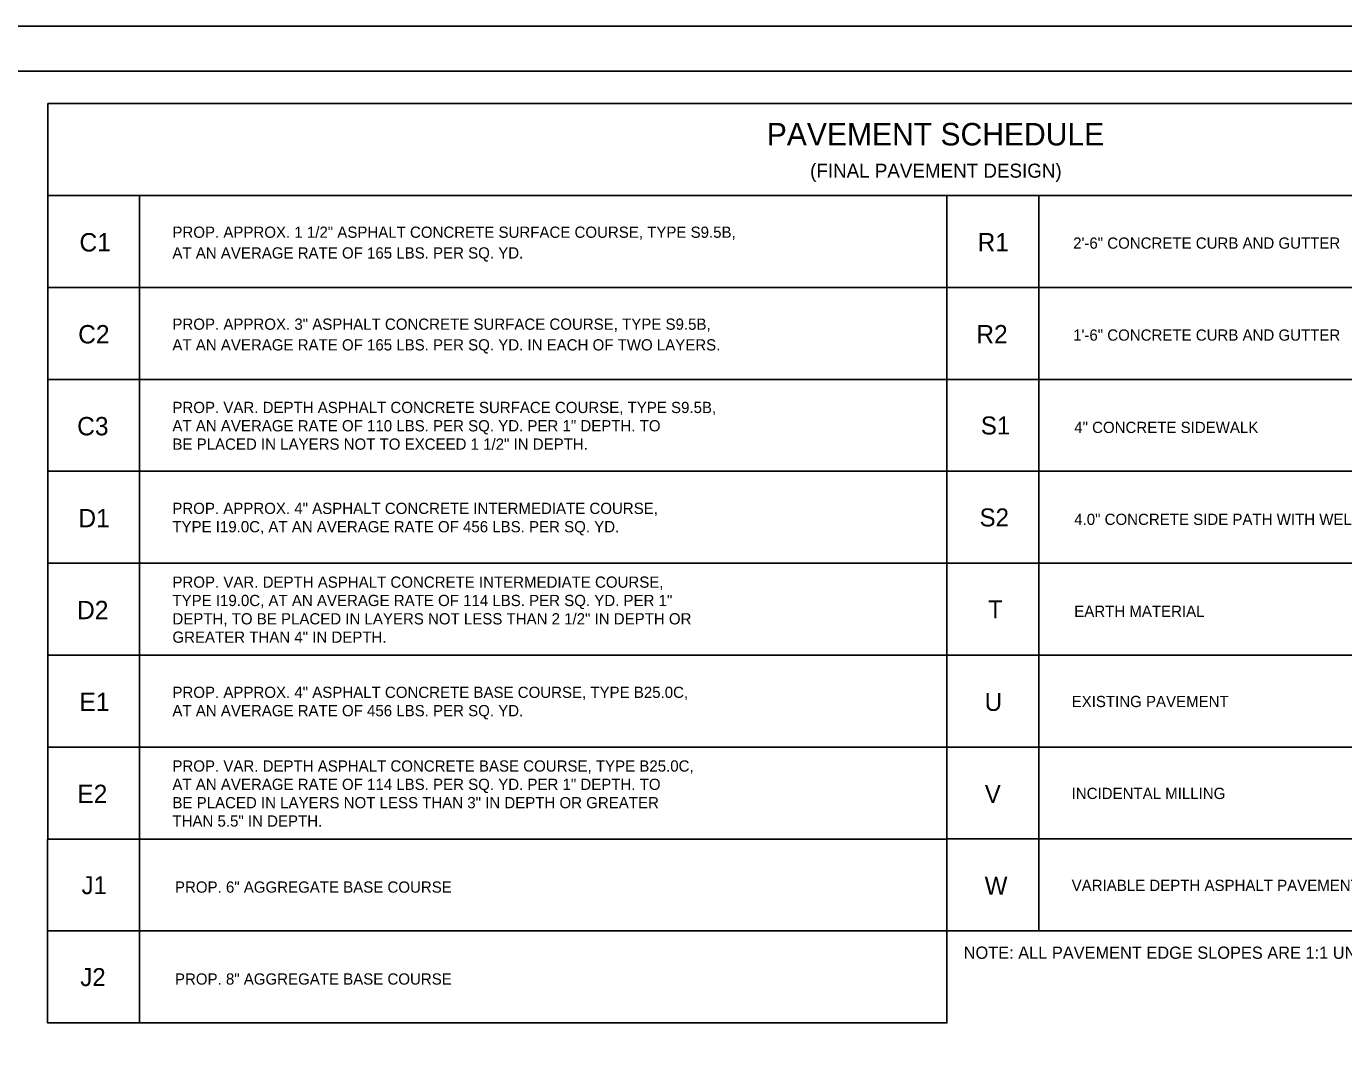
# Model space of a CAD drawing. Extents: x 1487909 to 1489267, y 497866 to 499814.
# Drawn here: x 1488908.3 to 1488981.6, y 498401.4 to 498458 of the extents above; entities that cross this region are included whole.
import ezdxf

# ---------------------------------------------------------------- set-up
doc = ezdxf.new("R2010")
doc.units = 0
for name, color, linetype in [('Prop Pavement Schedule Description CELL', 7, 'Continuous'), ('Sheet Plot Border Outside CELL', 7, 'Continuous'), ('Sheet Typical CELL', 7, 'Continuous'), ('Typical Slope Point Local CELL', 7, 'Continuous')]:
    doc.layers.add(name, color=color, linetype=linetype)

msp = doc.modelspace()

# ---------------------------------------------------------------- linework, layer by layer
at = {"layer": 'Prop Pavement Schedule Description CELL'}
for points in [[(1488914.641, 498443.431), (1488909.528, 498443.431), (1488909.528, 498448.546), (1488959.528, 498448.546), (1488959.528, 498443.431), (1488914.641, 498443.431), (1488914.641, 498448.546)], [(1488964.641, 498443.433), (1488959.528, 498443.433), (1488959.528, 498448.547), (1489009.529, 498448.547), (1489009.529, 498443.433), (1488964.641, 498443.433), (1488964.641, 498448.547)], [(1488914.641, 498438.316), (1488909.528, 498438.316), (1488909.528, 498443.431), (1488959.528, 498443.431), (1488959.528, 498438.316), (1488914.641, 498438.316), (1488914.641, 498443.431)], [(1488964.641, 498438.318), (1488959.528, 498438.318), (1488959.528, 498443.432), (1489009.529, 498443.432), (1489009.529, 498438.318), (1488964.641, 498438.318), (1488964.641, 498443.432)], [(1488914.641, 498433.204), (1488909.528, 498433.204), (1488909.528, 498438.317), (1488959.528, 498438.317), (1488959.528, 498433.204), (1488914.641, 498433.204), (1488914.641, 498438.317)], [(1488914.641, 498428.09), (1488909.528, 498428.09), (1488909.528, 498433.204), (1488959.528, 498433.204), (1488959.528, 498428.09), (1488914.641, 498428.09), (1488914.641, 498433.204)], [(1488914.641, 498422.977), (1488909.528, 498422.977), (1488909.528, 498428.09), (1488959.529, 498428.09), (1488959.529, 498422.977), (1488914.641, 498422.977), (1488914.641, 498428.09)]]:
    msp.add_lwpolyline(points, dxfattribs=at)
at = {"layer": 'Sheet Plot Border Outside CELL'}
msp.add_lwpolyline([(1489051.664, 498457.953), (1488883.264, 498457.953), (1488883.264, 498347.953), (1489051.664, 498347.953)], close=True, dxfattribs=at)
at = {"layer": 'Sheet Typical CELL'}
msp.add_lwpolyline([(1489049.964, 498455.453), (1488899.964, 498455.453), (1488899.964, 498350.453), (1489049.964, 498350.453)], close=True, dxfattribs=at)
at = {"layer": 'Typical Slope Point Local CELL'}
msp.add_line((1488958.227, 498417.863), (1488958.227, 498417.863), dxfattribs=at)
msp.add_lwpolyline([(1488909.528, 498453.658), (1489009.529, 498453.658), (1489009.529, 498448.546), (1488909.528, 498448.546)], close=True, dxfattribs=at)
for points in [[(1488964.641, 498433.205), (1488959.528, 498433.205), (1488959.528, 498438.318), (1489009.528, 498438.318), (1489009.528, 498433.205), (1488964.641, 498433.205), (1488964.641, 498438.318)], [(1488964.641, 498428.091), (1488959.528, 498428.091), (1488959.528, 498433.205), (1489009.528, 498433.205), (1489009.528, 498428.091), (1488964.641, 498428.091), (1488964.641, 498433.205)], [(1488964.641, 498422.978), (1488959.528, 498422.978), (1488959.528, 498428.091), (1489009.528, 498428.091), (1489009.528, 498422.978), (1488964.641, 498422.978), (1488964.641, 498428.091)], [(1488914.641, 498417.863), (1488909.528, 498417.863), (1488909.528, 498422.977), (1488959.528, 498422.977), (1488959.528, 498417.863), (1488914.641, 498417.863), (1488914.641, 498422.977)], [(1488964.641, 498417.864), (1488959.528, 498417.864), (1488959.528, 498422.978), (1489009.528, 498422.978), (1489009.528, 498417.864), (1488964.641, 498417.864), (1488964.641, 498422.978)], [(1488914.641, 498412.75), (1488909.528, 498412.75), (1488909.528, 498417.863), (1488959.528, 498417.863), (1488959.528, 498412.75), (1488914.641, 498412.75), (1488914.641, 498417.863)], [(1488964.641, 498412.751), (1488959.528, 498412.751), (1488959.528, 498417.864), (1489009.528, 498417.864), (1489009.528, 498412.751), (1488964.641, 498412.751), (1488964.641, 498417.864)], [(1488914.64, 498407.636), (1488909.527, 498407.636), (1488909.527, 498412.75), (1488959.527, 498412.75), (1488959.527, 498407.636), (1488914.64, 498407.636), (1488914.64, 498412.75)], [(1488964.641, 498407.637), (1488959.528, 498407.637), (1488959.528, 498412.751), (1489009.528, 498412.751), (1489009.528, 498407.637), (1488964.641, 498407.637), (1488964.641, 498412.751)], [(1488914.639, 498402.523), (1488909.526, 498402.523), (1488909.526, 498407.636), (1488959.526, 498407.636), (1488959.526, 498402.523), (1488914.639, 498402.523), (1488914.639, 498407.636)]]:
    msp.add_lwpolyline(points, dxfattribs=at)

# ---------------------------------------------------------------- texts
at = {"layer": 'Prop Pavement Schedule Description CELL'}
for s, height, p in [('PROP. APPROX. 1 1/2" ASPHALT CONCRETE SURFACE COURSE, TYPE S9.5B,', 0.625, (1488916.464, 498446.189)), ('C1', 1.0208, (1488911.295, 498445.431)), ('R1', 1.0208, (1488961.233, 498445.432)), ('2\'-6" CONCRETE CURB AND GUTTER', 0.625, (1488966.547, 498445.584)), ('AT AN AVERAGE RATE OF 165 LBS. PER SQ. YD. ', 0.625, (1488916.464, 498445.037)), ('PROP. APPROX. 3" ASPHALT CONCRETE SURFACE COURSE, TYPE S9.5B,', 0.625, (1488916.464, 498441.074)), ('C2', 1.0208, (1488911.224, 498440.316)), ('R2', 1.0208, (1488961.161, 498440.317)), ('1\'-6" CONCRETE CURB AND GUTTER', 0.625, (1488966.547, 498440.469)), ('AT AN AVERAGE RATE OF 165 LBS. PER SQ. YD. IN EACH OF TWO LAYERS.', 0.625, (1488916.464, 498439.923)), ('PROP. APPROX. 4" ASPHALT CONCRETE INTERMEDIATE COURSE,', 0.625, (1488916.459, 498430.829)), ('D1', 1.0208, (1488911.233, 498430.09)), ('TYPE I19.0C, AT AN AVERAGE RATE OF 456 LBS. PER SQ. YD.', 0.625, (1488916.459, 498429.809))]:
    msp.add_text(s, height=height, dxfattribs=at).set_placement(p)
for s, height, p in [('PROP. VAR. DEPTH ASPHALT CONCRETE SURFACE COURSE, TYPE S9.5B,', 0.625, (1488916.464, 498436.442)), ('C3', 1.0208, (1488911.167, 498435.204)), ('AT AN AVERAGE RATE OF 110 LBS. PER SQ. YD. PER 1" DEPTH. TO', 0.625, (1488916.464, 498435.423)), ('BE PLACED IN LAYERS NOT TO EXCEED 1 1/2" IN DEPTH.', 0.625, (1488916.464, 498434.403)), ('PROP. VAR. DEPTH ASPHALT CONCRETE INTERMEDIATE COURSE,', 0.625, (1488916.464, 498426.726)), ('TYPE I19.0C, AT AN AVERAGE RATE OF 114 LBS. PER SQ. YD. PER 1" ', 0.625, (1488916.464, 498425.706)), ('D2', 1.0208, (1488911.161, 498424.977)), ('DEPTH, TO BE PLACED IN LAYERS NOT LESS THAN 2 1/2" IN DEPTH OR', 0.625, (1488916.464, 498424.686)), ('GREATER THAN 4" IN DEPTH.', 0.625, (1488916.464, 498423.666))]:
    msp.add_text(s, height=height, rotation=360, dxfattribs=at).set_placement(p)
at = {"layer": 'Typical Slope Point Local CELL'}
for s, height, p in [('PAVEMENT SCHEDULE', 1.25, (1488949.511, 498451.328)), ('(FINAL PAVEMENT DESIGN)', 0.78125, (1488951.921, 498449.533)), ('S1', 1, (1488961.414, 498435.252)), ('4" CONCRETE SIDEWALK', 0.625, (1488966.607, 498435.333)), ('S2', 1, (1488961.343, 498430.138)), ('4.0" CONCRETE SIDE PATH WITH WELDED WIRE MESH', 0.625, (1488966.607, 498430.219)), ('T', 1, (1488961.811, 498425.025)), ('EARTH MATERIAL', 0.625, (1488966.607, 498425.106)), ('PROP. APPROX. 4" ASPHALT CONCRETE BASE COURSE, TYPE B25.0C,', 0.625, (1488916.464, 498420.597)), ('E1', 1.0208, (1488911.295, 498419.862)), ('U', 1, (1488961.629, 498419.875)), ('EXISTING PAVEMENT', 0.625, (1488966.464, 498420.087)), ('AT AN AVERAGE RATE OF 456 LBS. PER SQ. YD.', 0.625, (1488916.464, 498419.577)), ('PROP. VAR. DEPTH ASPHALT CONCRETE BASE COURSE, TYPE B25.0C,', 0.625, (1488916.464, 498416.499)), ('AT AN AVERAGE RATE OF 114 LBS. PER SQ. YD. PER 1" DEPTH. TO', 0.625, (1488916.464, 498415.479)), ('E2', 1.0208, (1488911.176, 498414.749)), ('V', 1, (1488961.633, 498414.761)), ('INCIDENTAL MILLING', 0.625, (1488966.464, 498414.974)), ('BE PLACED IN LAYERS NOT LESS THAN 3" IN DEPTH OR GREATER', 0.625, (1488916.464, 498414.459)), ('THAN 5.5" IN DEPTH.', 0.625, (1488916.464, 498413.439)), ('J1', 1, (1488911.413, 498409.683)), ('PROP. 6" AGGREGATE BASE COURSE', 0.625, (1488916.606, 498409.764)), ('W', 1, (1488961.629, 498409.648)), ('VARIABLE DEPTH ASPHALT PAVEMENT (SEE WEDGING DETAILS)', 0.625, (1488966.464, 498409.86)), ('NOTE: ALL PAVEMENT EDGE SLOPES ARE 1:1 UNLESS SHOWN OTHERWISE.', 0.68021, (1488960.46, 498406.087)), ('J2', 1, (1488911.341, 498404.569)), ('PROP. 8" AGGREGATE BASE COURSE', 0.625, (1488916.605, 498404.651))]:
    msp.add_text(s, height=height, dxfattribs=at).set_placement(p)

doc.saveas('drawing.dxf')
